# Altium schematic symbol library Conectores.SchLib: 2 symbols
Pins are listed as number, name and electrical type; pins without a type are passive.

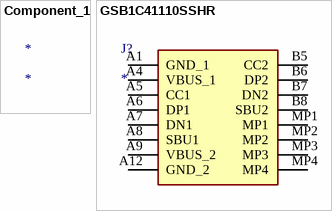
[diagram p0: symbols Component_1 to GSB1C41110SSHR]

## Component_1
designator *

## GSB1C41110SSHR
designator J?
Connector; Manufacturer_Name: Amphenol Communications Solutions; Manufacturer_Part_Number: GSB1C41110SSHR; Description: USB2.0
footprint GSB1C41110SSHR
pins: A1 GND_1, A4 VBUS_1, A5 CC1, A6 DP1, A7 DN1, A8 SBU1, A9 VBUS_2, A12 GND_2, B5 CC2, B6 DP2, B7 DN2, B8 SBU2, MP1, MP2, MP3, MP4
